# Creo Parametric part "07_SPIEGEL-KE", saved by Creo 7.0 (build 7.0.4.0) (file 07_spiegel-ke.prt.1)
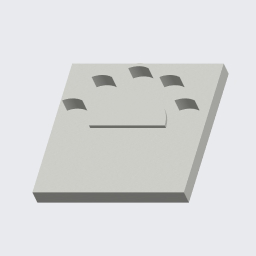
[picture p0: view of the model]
Units: millimeter Kilogram Sec (mmKs); MM, KILOGRAM, SECS
Materials in the file: S235JRG2

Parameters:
  PTC_MATERIAL_NAME = "S235JRG2"
  BENENNUNG = "XXX"
  DATUM = "XX.XX.XX"
  ERSTELLER = "ARINDA"
  TEILETYP = "Fertigungsteil"
  SELECT_EN_NAME = "S235JRG2"
  SELECT_DIN_NAME = "RSt37-2"
  SELECT_DIN_NUMBER = "1.0038"
  SELECT_ASTM_NAME = "A 283 M Grade 2"
  MATERIAL_GROUP = "ME_ST_Baustahl"
  STANDARD_EN_DELIVERYSPEC = "DIN EN 10025"
  STANDARD_DIN_DELIVERYSPEC = "DIN 17100"

Other parameters: MASSE

Created from: ARINDA-STARTTEIL.PRT

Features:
  1. coordinate system "CS0"
  2. datum plane "DTM1", "T_RECHTS_Y-Z"
  3. datum plane "DTM2", "T_OBEN_X-Z"
  4. datum plane "DTM3", "T_VORNE_X-Y"
  5. datum axis "T_X-ACHSE"
  6. datum axis "A_1"
  7. datum axis "A_2"
  8. extrusion "Profil 1"
  9. extrusion "Profil 3"
  10. sketch "Skizze 1"
  11. pattern "Muster 1"
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
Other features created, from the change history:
  extrusion "Profil 2"
  extrusion "Profil 2 [22]"
  extrusion "Profil 2 [23]"
  extrusion "Profil 2 [25]"
  extrusion "Profil 2 [26]"
  hole "Bohrung 1"
  pattern "Muster 2" (3 times)
  hole "Bohrung 1 [21]" (2 times)
  hole "Bohrung 1 [22]" (3 times)
  hole "Bohrung 1 [23]" (3 times)
  hole "Bohrung 1 [25]" (3 times)
  hole "Bohrung 1 [26]" (3 times)
  extrusion "Profil 3" (5 times)
  extrusion "Profil 4"
  mirror "Spiegeln 1" (4 times)
  extrusion "Profil 3 (2)"
  pattern "Muster 1 (2)" (3 times)
  extrusion "Profil 2 (2) [1]" (3 times)
  extrusion "Profil 2 (2) [22]" (3 times)
  extrusion "Profil 2 (2) [23]" (3 times)
  extrusion "Profil 2 (2) [25]" (3 times)
  extrusion "Profil 2 (2) [26]" (3 times)

Other named items: T_BASIC, GRUNDPLATTE, MUSTER, STEG, HALBKREIS, T_Y-ACHSE, T_Z-ACHSE

Layers: 00_STD-ACHSEN, 00_STD-EBENEN, 00_STD-KOORDSYS, 01_ACHSEN, 01_KURVEN, KURVENELEMENTE, VOLUMENGEOMETRIE

Surfaces: 15 plane, 11 cylinder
